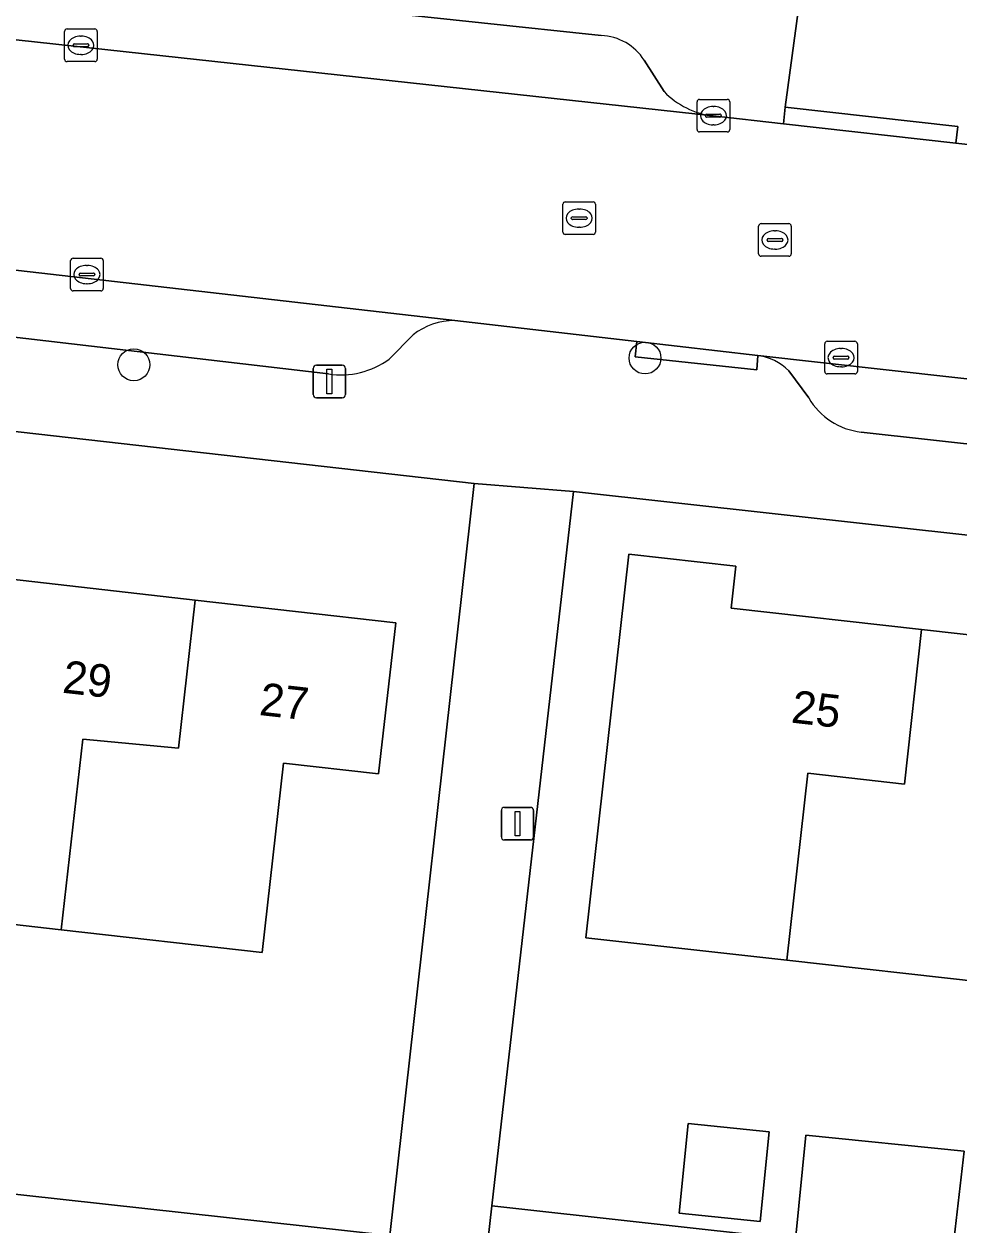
# Model space of a CAD drawing. Extents: x 162082 to 163401, y 388089 to 388636.
# Drawn here: x 162779.64 to 162808.31, y 388312.65 to 388349.48 of the extents above; entities that cross this region are included whole.
import ezdxf

# ---------------------------------------------------------------- set-up
doc = ezdxf.new("R2010")
doc.units = 0
for name, color, linetype in [('IMGEO_Boom', 7, 'Continuous'), ('IMGEO_Erf', 7, 'Continuous'), ('IMGEO_Kolk', 7, 'Continuous'), ('IMGEO_Lichtmast', 7, 'Continuous'), ('IMGEO_Pand', 7, 'Continuous'), ('IMGEO_Pand_nummerreeks', 7, 'Continuous'), ('IMGEO_Parkeervlak_open', 7, 'Continuous'), ('IMGEO_Rijbaan_lokaal_open', 7, 'Continuous'), ('IMGEO_Rioolput', 7, 'Continuous'), ('IMGEO_Voetpad_open', 7, 'Continuous')]:
    doc.layers.add(name, color=color, linetype=linetype)

msp = doc.modelspace()

# ---------------------------------------------------------------- linework, layer by layer
at = {"layer": 'IMGEO_Boom'}
for centre in [(162783.009, 388339.03), (162798.685, 388339.235)]:
    msp.add_circle(centre, 0.489, dxfattribs=at)
at = {"layer": 'IMGEO_Erf'}
for points in [[(162793.443, 388335.388), (162740.3, 388341.413)], [(162738.154, 388339.384), (162735.799, 388318.4), (162759.124, 388315.835), (162759.493, 388319.088), (162762.372, 388318.761), (162762.003, 388315.508), (162790.857, 388312.329), (162793.443, 388335.388)], [(162882.015, 388325.663), (162868.576, 388327.156), (162796.49, 388335.147), (162793.989, 388313.237), (162803.295, 388312.21), (162803.618, 388315.408), (162808.467, 388314.919), (162808.108, 388311.725)], [(162809.05, 388320.097), (162803.032, 388320.771), (162796.87, 388321.461), (162798.186, 388333.222), (162801.466, 388332.855), (162801.322, 388331.563), (162807.167, 388330.908), (162813.182, 388330.235)]]:
    msp.add_lwpolyline(points, dxfattribs=at)
for points in [[(162742.742, 388336.592), (162748.89, 388335.895), (162754.891, 388335.215), (162760.89, 388334.534), (162766.891, 388333.854), (162772.892, 388333.174), (162778.893, 388332.493), (162784.893, 388331.813), (162791.04, 388331.116), (162790.515, 388326.482), (162787.602, 388326.812), (162786.944, 388321.006), (162780.783, 388321.705), (162774.767, 388322.387), (162768.752, 388323.069), (162762.737, 388323.751), (162756.721, 388324.433), (162750.705, 388325.115), (162744.69, 388325.797), (162738.524, 388326.496), (162739.191, 388332.377), (162742.225, 388332.033)], [(162802.219, 388312.762), (162799.728, 388313.014), (162800.005, 388315.764), (162802.496, 388315.512)]]:
    msp.add_lwpolyline(points, close=True, dxfattribs=at)
at = {"layer": 'IMGEO_Kolk'}
for p, q in [((162780.886, 388348.399), (162780.886, 388349.251)), ((162780.961, 388349.325), (162781.813, 388349.325)), ((162781.374, 388349.105), (162781.399, 388349.105)), ((162781.887, 388349.251), (162781.887, 388348.399)), ((162781.145, 388348.819), (162781.145, 388348.831)), ((162781.583, 388348.782), (162781.185, 388348.782)), ((162781.188, 388348.868), (162781.586, 388348.868)), ((162781.629, 388348.831), (162781.629, 388348.819)), ((162781.813, 388348.325), (162780.961, 388348.325)), ((162781.397, 388348.545), (162781.372, 388348.545)), ((162800.357, 388347.167), (162801.209, 388347.167)), ((162800.282, 388346.241), (162800.282, 388347.093)), ((162800.77, 388346.947), (162800.795, 388346.947)), ((162801.283, 388347.093), (162801.283, 388346.241)), ((162800.541, 388346.661), (162800.541, 388346.673)), ((162800.979, 388346.624), (162800.581, 388346.624)), ((162800.584, 388346.71), (162800.982, 388346.71)), ((162800.793, 388346.387), (162800.768, 388346.387)), ((162801.025, 388346.673), (162801.025, 388346.661)), ((162801.209, 388346.167), (162800.357, 388346.167)), ((162781.071, 388341.369), (162781.071, 388342.221)), ((162781.146, 388342.295), (162781.998, 388342.295)), ((162781.559, 388342.075), (162781.584, 388342.075)), ((162782.072, 388342.221), (162782.072, 388341.369)), ((162781.33, 388341.789), (162781.33, 388341.801)), ((162781.768, 388341.752), (162781.37, 388341.752)), ((162781.373, 388341.838), (162781.771, 388341.838)), ((162781.814, 388341.801), (162781.814, 388341.789)), ((162781.998, 388341.295), (162781.146, 388341.295)), ((162781.582, 388341.515), (162781.557, 388341.515)), ((162804.196, 388338.822), (162804.196, 388339.674)), ((162804.271, 388339.748), (162805.123, 388339.748)), ((162804.684, 388339.528), (162804.709, 388339.528)), ((162805.197, 388339.674), (162805.197, 388338.822)), ((162804.455, 388339.242), (162804.455, 388339.254)), ((162804.893, 388339.205), (162804.495, 388339.205)), ((162804.498, 388339.291), (162804.896, 388339.291)), ((162804.939, 388339.254), (162804.939, 388339.242)), ((162805.123, 388338.748), (162804.271, 388338.748)), ((162804.707, 388338.968), (162804.682, 388338.968))]:
    msp.add_line(p, q, dxfattribs=at)
for points in [[(162780.886, 388348.399), (162780.886, 388349.251)], [(162780.961, 388349.325), (162781.813, 388349.325)], [(162781.887, 388349.251), (162781.887, 388348.399)], [(162781.813, 388348.325), (162780.961, 388348.325)], [(162800.357, 388347.167), (162801.209, 388347.167)], [(162800.282, 388346.241), (162800.282, 388347.093)], [(162801.283, 388347.093), (162801.283, 388346.241)], [(162801.209, 388346.167), (162800.357, 388346.167)], [(162781.071, 388341.369), (162781.071, 388342.221)], [(162781.146, 388342.295), (162781.998, 388342.295)], [(162782.072, 388342.221), (162782.072, 388341.369)], [(162781.998, 388341.295), (162781.146, 388341.295)], [(162804.196, 388338.822), (162804.196, 388339.674)], [(162804.271, 388339.748), (162805.123, 388339.748)], [(162805.197, 388339.674), (162805.197, 388338.822)], [(162805.123, 388338.748), (162804.271, 388338.748)]]:
    msp.add_lwpolyline(points, dxfattribs=at)
for centre, radius, start, end in [((162780.963, 388349.249), 0.0765, 91.552, 178.448), ((162780.963, 388349.249), 0.0765, 91.552, 178.448), ((162781.811, 388349.249), 0.0765, 1.552, 88.448), ((162781.811, 388349.249), 0.0765, 1.552, 88.448), ((162781.185, 388348.828), 0.0403, 85.8775, 175.7526), ((162781.182, 388348.818), 0.0366, 178.938, 274.7102), ((162781.586, 388348.825), 0.043, 264.8664, 352.4533), ((162781.59, 388348.83), 0.0386, 1.7309, 96.639), ((162780.963, 388348.401), 0.0765, 181.552, 268.448), ((162780.963, 388348.401), 0.0765, 181.552, 268.448), ((162781.811, 388348.401), 0.0765, 271.552, 358.448), ((162781.811, 388348.401), 0.0765, 271.552, 358.448), ((162800.359, 388347.091), 0.0765, 91.552, 178.448), ((162800.359, 388347.091), 0.0765, 91.552, 178.448), ((162801.207, 388347.091), 0.0765, 1.552, 88.448), ((162801.207, 388347.091), 0.0765, 1.552, 88.448), ((162800.581, 388346.67), 0.0403, 85.8775, 175.7526), ((162800.578, 388346.66), 0.0366, 178.938, 274.7102), ((162800.982, 388346.667), 0.043, 264.8664, 352.4533), ((162800.986, 388346.672), 0.0386, 1.7309, 96.639), ((162800.359, 388346.243), 0.0765, 181.552, 268.448), ((162800.359, 388346.243), 0.0765, 181.552, 268.448), ((162801.207, 388346.243), 0.0765, 271.552, 358.448), ((162801.207, 388346.243), 0.0765, 271.552, 358.448), ((162781.148, 388342.219), 0.0765, 91.552, 178.448), ((162781.148, 388342.219), 0.0765, 91.552, 178.448), ((162781.996, 388342.219), 0.0765, 1.552, 88.448), ((162781.996, 388342.219), 0.0765, 1.552, 88.448), ((162781.37, 388341.798), 0.0403, 85.8775, 175.7526), ((162781.367, 388341.788), 0.0366, 178.938, 274.7102), ((162781.771, 388341.795), 0.043, 264.8664, 352.4533), ((162781.775, 388341.8), 0.0386, 1.7309, 96.639), ((162781.148, 388341.371), 0.0765, 181.552, 268.448), ((162781.148, 388341.371), 0.0765, 181.552, 268.448), ((162781.996, 388341.371), 0.0765, 271.552, 358.448), ((162781.996, 388341.371), 0.0765, 271.552, 358.448), ((162804.273, 388339.672), 0.0765, 91.552, 178.448), ((162804.273, 388339.672), 0.0765, 91.552, 178.448), ((162805.121, 388339.672), 0.0765, 1.552, 88.448), ((162805.121, 388339.672), 0.0765, 1.552, 88.448), ((162804.495, 388339.251), 0.0403, 85.8775, 175.7526), ((162804.492, 388339.241), 0.0366, 178.938, 274.7102), ((162804.896, 388339.248), 0.043, 264.8664, 352.4533), ((162804.9, 388339.253), 0.0386, 1.7309, 96.639), ((162804.273, 388338.824), 0.0765, 181.552, 268.448), ((162804.273, 388338.824), 0.0765, 181.552, 268.448), ((162805.121, 388338.824), 0.0765, 271.552, 358.448), ((162805.121, 388338.824), 0.0765, 271.552, 358.448)]:
    msp.add_arc(centre, radius, start, end, dxfattribs=at)
for centre, major_axis, ratio, start_param, end_param in [((162781.373, 388348.825), (-0.387, 0.002), 0.722429, 4.712389, 7.853982), ((162781.398, 388348.825), (-0.39, 0.002), 0.717154, 1.570796, 4.712389), ((162800.769, 388346.667), (-0.387, 0.002), 0.722429, 4.712389, 7.853982), ((162800.794, 388346.667), (-0.39, 0.002), 0.717154, 1.570796, 4.712389), ((162781.558, 388341.795), (-0.387, 0.002), 0.722429, 4.712389, 7.853982), ((162781.583, 388341.795), (-0.39, 0.002), 0.717154, 1.570796, 4.712389), ((162804.683, 388339.248), (-0.387, 0.002), 0.722429, 4.712389, 7.853982), ((162804.708, 388339.248), (-0.39, 0.002), 0.717154, 1.570796, 4.712389)]:
    msp.add_ellipse(centre, major_axis=major_axis, ratio=ratio, start_param=start_param, end_param=end_param, dxfattribs=at)
at = {"layer": 'IMGEO_Lichtmast'}
for p, q in [((162788.609, 388339.017), (162789.399, 388339.017)), ((162789.399, 388339.017), (162788.609, 388339.017)), ((162788.509, 388338.117), (162788.509, 388338.917)), ((162788.509, 388338.917), (162788.509, 388338.117)), ((162789.499, 388338.917), (162789.499, 388338.117)), ((162789.499, 388338.117), (162789.499, 388338.917)), ((162789.399, 388338.017), (162788.609, 388338.017)), ((162788.609, 388338.017), (162789.399, 388338.017)), ((162794.379, 388325.457), (162795.169, 388325.457)), ((162795.169, 388325.457), (162794.379, 388325.457)), ((162794.279, 388324.557), (162794.279, 388325.357)), ((162794.279, 388325.357), (162794.279, 388324.557)), ((162795.269, 388325.357), (162795.269, 388324.557)), ((162795.269, 388324.557), (162795.269, 388325.357)), ((162795.169, 388324.457), (162794.379, 388324.457)), ((162794.379, 388324.457), (162795.169, 388324.457))]:
    msp.add_line(p, q, dxfattribs=at)
for points in [[(162788.929, 388338.892), (162789.079, 388338.892), (162789.079, 388338.142), (162788.929, 388338.142), (162788.929, 388338.892)], [(162794.699, 388325.332), (162794.849, 388325.332), (162794.849, 388324.582), (162794.699, 388324.582), (162794.699, 388325.332)]]:
    msp.add_lwpolyline(points, dxfattribs=at)
for centre, start, end in [((162788.609, 388338.917), 90, 180), ((162788.609, 388338.917), 90, 180), ((162789.399, 388338.917), 0, 90), ((162789.399, 388338.917), 360, 90), ((162788.609, 388338.117), 180, 270), ((162788.609, 388338.117), 180, 270), ((162789.399, 388338.117), 270, 0), ((162789.399, 388338.117), 270, 0), ((162794.379, 388325.357), 90, 180), ((162794.379, 388325.357), 90, 180), ((162795.169, 388325.357), 0, 90), ((162795.169, 388325.357), 360, 90), ((162794.379, 388324.557), 180, 270), ((162794.379, 388324.557), 180, 270), ((162795.169, 388324.557), 270, 0), ((162795.169, 388324.557), 270, 0)]:
    msp.add_arc(centre, 0.1, start, end, dxfattribs=at)
at = {"layer": 'IMGEO_Pand'}
for points in [[(162803.032, 388320.771), (162803.677, 388326.504), (162806.637, 388326.173), (162807.167, 388330.908), (162801.322, 388331.563), (162801.466, 388332.855), (162798.186, 388333.222), (162796.87, 388321.461)], [(162780.783, 388321.705), (162781.444, 388327.548), (162784.379, 388327.269), (162784.893, 388331.813), (162778.893, 388332.493), (162778.379, 388327.947), (162775.428, 388328.23), (162774.767, 388322.387)], [(162780.783, 388321.705), (162786.944, 388321.006), (162787.602, 388326.812), (162790.515, 388326.482), (162791.04, 388331.116), (162784.893, 388331.813), (162784.379, 388327.269), (162781.444, 388327.548)], [(162809.05, 388320.097), (162809.695, 388325.83), (162812.651, 388325.499), (162813.182, 388330.235), (162807.167, 388330.908), (162806.637, 388326.173), (162803.677, 388326.504), (162803.032, 388320.771)], [(162799.728, 388313.014), (162802.219, 388312.762), (162802.496, 388315.512), (162800.005, 388315.764)], [(162808.467, 388314.919), (162803.618, 388315.408), (162803.295, 388312.21), (162808.108, 388311.725)]]:
    msp.add_lwpolyline(points, close=True, dxfattribs=at)
at = {"layer": 'IMGEO_Parkeervlak_open'}
for points in [[(162797.34, 388349.123), (162749.629, 388354.18)], [(162746.114, 388352.626), (162800.77, 388346.657)], [(162799.271, 388347.407), (162798.659, 388348.367)], [(162792.851, 388340.382), (162745.211, 388345.846)], [(162747.992, 388343.538), (162788.983, 388338.749)], [(162790.84, 388339.201), (162791.572, 388339.942)], [(162880.401, 388330.569), (162802.146, 388339.314)], [(162803.094, 388338.843), (162803.705, 388338.011)], [(162805.311, 388336.967), (162876.952, 388329.043)]]:
    msp.add_lwpolyline(points, dxfattribs=at)
for centre, radius, start, end in [((162797.285, 388347.499), 1.625, 32.2862, 88.0745), ((162801.078, 388349.145), 2.507, 223.8907, 262.9486), ((162792.816, 388338.406), 1.976, 88.9736, 128.9948), ((162789.367, 388341.211), 2.492, 261.1303, 306.2296), ((162801.926, 388337.682), 1.647, 44.835, 82.3254), ((162805.545, 388339.084), 2.13, 210.2575, 263.6897)]:
    msp.add_arc(centre, radius, start, end, dxfattribs=at)
at = {"layer": 'IMGEO_Rijbaan_lokaal_open'}
for points in [[(162808.22, 388345.824), (162802.929, 388346.416), (162800.77, 388346.657), (162746.114, 388352.626), (162744.978, 388352.71), (162731.668, 388354.343), (162731.252, 388354.396), (162702.229, 388357.552), (162700.084, 388357.788), (162695.039, 388358.344), (162654.13, 388362.855), (162618.656, 388366.803)], [(162618.083, 388359.792), (162618.494, 388359.75), (162651.027, 388356.187), (162671.349, 388353.951), (162718.747, 388349.06), (162720.569, 388348.856), (162722.81, 388348.605), (162722.944, 388348.631), (162744.531, 388345.945), (162744.575, 388345.916), (162745.211, 388345.846), (162792.851, 388340.382), (162798.436, 388339.741), (162802.146, 388339.314), (162880.401, 388330.569)], [(162880.788, 388337.712), (162871.19, 388338.785), (162847.751, 388341.405), (162843.975, 388341.827), (162808.22, 388345.824)]]:
    msp.add_lwpolyline(points, dxfattribs=at)
at = {"layer": 'IMGEO_Rioolput'}
for p, q in [((162796.166, 388343.098), (162796.166, 388343.95)), ((162796.241, 388344.024), (162797.093, 388344.024)), ((162796.654, 388343.804), (162796.679, 388343.804)), ((162797.167, 388343.95), (162797.167, 388343.098)), ((162796.425, 388343.518), (162796.425, 388343.53)), ((162796.863, 388343.481), (162796.465, 388343.481)), ((162796.468, 388343.567), (162796.866, 388343.567)), ((162796.909, 388343.53), (162796.909, 388343.518)), ((162796.677, 388343.244), (162796.652, 388343.244)), ((162802.169, 388342.43), (162802.169, 388343.282)), ((162802.244, 388343.356), (162803.096, 388343.356)), ((162802.657, 388343.136), (162802.682, 388343.136)), ((162803.17, 388343.282), (162803.17, 388342.43)), ((162797.093, 388343.024), (162796.241, 388343.024)), ((162802.428, 388342.85), (162802.428, 388342.862)), ((162802.866, 388342.813), (162802.468, 388342.813)), ((162802.471, 388342.899), (162802.869, 388342.899)), ((162802.912, 388342.862), (162802.912, 388342.85)), ((162803.096, 388342.356), (162802.244, 388342.356)), ((162802.68, 388342.576), (162802.655, 388342.576))]:
    msp.add_line(p, q, dxfattribs=at)
for points in [[(162796.166, 388343.098), (162796.166, 388343.95)], [(162796.241, 388344.024), (162797.093, 388344.024)], [(162797.167, 388343.95), (162797.167, 388343.098)], [(162802.169, 388342.43), (162802.169, 388343.282)], [(162802.244, 388343.356), (162803.096, 388343.356)], [(162803.17, 388343.282), (162803.17, 388342.43)], [(162797.093, 388343.024), (162796.241, 388343.024)], [(162803.096, 388342.356), (162802.244, 388342.356)]]:
    msp.add_lwpolyline(points, dxfattribs=at)
for centre, radius, start, end in [((162796.243, 388343.948), 0.0765, 91.552, 178.448), ((162796.243, 388343.948), 0.0765, 91.552, 178.448), ((162797.091, 388343.948), 0.0765, 1.552, 88.448), ((162797.091, 388343.948), 0.0765, 1.552, 88.448), ((162796.465, 388343.527), 0.0403, 85.8775, 175.7526), ((162796.462, 388343.517), 0.0366, 178.938, 274.7102), ((162796.866, 388343.524), 0.043, 264.8664, 352.4533), ((162796.87, 388343.529), 0.0386, 1.7309, 96.639), ((162796.243, 388343.1), 0.0765, 181.552, 268.448), ((162796.243, 388343.1), 0.0765, 181.552, 268.448), ((162797.091, 388343.1), 0.0765, 271.552, 358.448), ((162797.091, 388343.1), 0.0765, 271.552, 358.448), ((162802.246, 388343.28), 0.0765, 91.552, 178.448), ((162802.246, 388343.28), 0.0765, 91.552, 178.448), ((162803.094, 388343.28), 0.0765, 1.552, 88.448), ((162803.094, 388343.28), 0.0765, 1.552, 88.448), ((162802.468, 388342.859), 0.0403, 85.8775, 175.7526), ((162802.465, 388342.849), 0.0366, 178.938, 274.7102), ((162802.869, 388342.856), 0.043, 264.8664, 352.4533), ((162802.873, 388342.861), 0.0386, 1.7309, 96.639), ((162802.246, 388342.432), 0.0765, 181.552, 268.448), ((162802.246, 388342.432), 0.0765, 181.552, 268.448), ((162803.094, 388342.432), 0.0765, 271.552, 358.448), ((162803.094, 388342.432), 0.0765, 271.552, 358.448)]:
    msp.add_arc(centre, radius, start, end, dxfattribs=at)
for centre, major_axis, ratio, start_param, end_param in [((162796.653, 388343.524), (-0.387, 0.002), 0.722429, 4.712389, 7.853982), ((162796.678, 388343.524), (-0.39, 0.002), 0.717154, 1.570796, 4.712389), ((162802.656, 388342.856), (-0.387, 0.002), 0.722429, 4.712389, 7.853982), ((162802.681, 388342.856), (-0.39, 0.002), 0.717154, 1.570796, 4.712389)]:
    msp.add_ellipse(centre, major_axis=major_axis, ratio=ratio, start_param=start_param, end_param=end_param, dxfattribs=at)
at = {"layer": 'IMGEO_Voetpad_open'}
for points in [[(162818.999, 388360.48), (162809.756, 388361.499), (162800.885, 388362.477), (162800.848, 388362.138), (162800.518, 388359.102), (162800.188, 388356.066), (162804.094, 388355.604), (162803.599, 388351.461), (162802.982, 388346.924), (162808.274, 388346.335), (162808.22, 388345.824), (162843.975, 388341.827), (162844.031, 388342.335), (162847.807, 388341.912), (162847.751, 388341.405), (162871.19, 388338.785), (162871.243, 388339.277), (162871.635, 388339.233), (162871.88, 388341.578)], [(162800.77, 388346.657), (162802.929, 388346.416), (162802.982, 388346.924), (162803.599, 388351.461), (162768.432, 388355.385)], [(162749.629, 388354.18), (162797.34, 388349.123)], [(162798.659, 388348.367), (162799.271, 388347.407)], [(162788.983, 388338.749), (162747.992, 388343.538)], [(162736.116, 388341.858), (162740.3, 388341.413), (162793.443, 388335.388), (162796.49, 388335.147), (162868.576, 388327.156), (162882.015, 388325.663), (162884.982, 388325.32), (162885.195, 388327.249), (162936.117, 388321.549), (162936.982, 388321.452), (162943.064, 388320.814)], [(162802.146, 388339.314), (162802.11, 388338.872), (162798.383, 388339.267), (162798.436, 388339.741), (162792.851, 388340.382)], [(162791.572, 388339.942), (162790.84, 388339.201)], [(162803.705, 388338.011), (162803.094, 388338.843)], [(162876.952, 388329.043), (162805.311, 388336.967)], [(162790.857, 388312.329), (162762.003, 388315.508), (162759.124, 388315.835), (162735.799, 388318.4), (162735.64, 388316.989), (162747.39, 388315.67), (162751.954, 388315.151), (162763.343, 388313.856), (162755.049, 388250.59)], [(162803.295, 388312.21), (162793.989, 388313.237), (162793.855, 388312.06)]]:
    msp.add_lwpolyline(points, dxfattribs=at)
for points in [[(162808.22, 388345.824), (162808.274, 388346.335), (162802.982, 388346.924), (162802.929, 388346.416)], [(162798.436, 388339.741), (162798.383, 388339.267), (162802.11, 388338.872), (162802.146, 388339.314)], [(162786.323, 388244.931), (162786.471, 388246.262), (162786.888, 388250), (162789.279, 388271.438), (162791.272, 388289.437), (162793.855, 388312.06), (162793.989, 388313.237), (162796.49, 388335.147), (162793.443, 388335.388), (162790.857, 388312.329), (162790.694, 388310.876), (162783.866, 388250), (162783.69, 388248.429), (162783.542, 388247.109), (162781.747, 388231.106), (162781.061, 388224.883), (162780.519, 388219.969), (162783.503, 388219.652)]]:
    msp.add_lwpolyline(points, close=True, dxfattribs=at)
for centre, radius, start, end in [((162797.285, 388347.499), 1.625, 32.2862, 88.0745), ((162801.078, 388349.145), 2.507, 223.8907, 262.9486), ((162792.816, 388338.406), 1.976, 88.9736, 128.9948), ((162789.367, 388341.211), 2.492, 261.1303, 306.2296), ((162801.926, 388337.682), 1.647, 44.835, 82.3254), ((162805.545, 388339.084), 2.13, 210.2575, 263.6897)]:
    msp.add_arc(centre, radius, start, end, dxfattribs=at)

# ---------------------------------------------------------------- texts
at = {"layer": 'IMGEO_Pand_nummerreeks'}
for s, rotation, p in [('29', 353.5315, (162780.793, 388328.976)), ('27', 353.5315, (162786.831, 388328.292)), ('25', 353.6094, (162803.143, 388328.059))]:
    msp.add_text(s, height=1, rotation=rotation, dxfattribs=at).set_placement(p)

doc.saveas('drawing.dxf')
